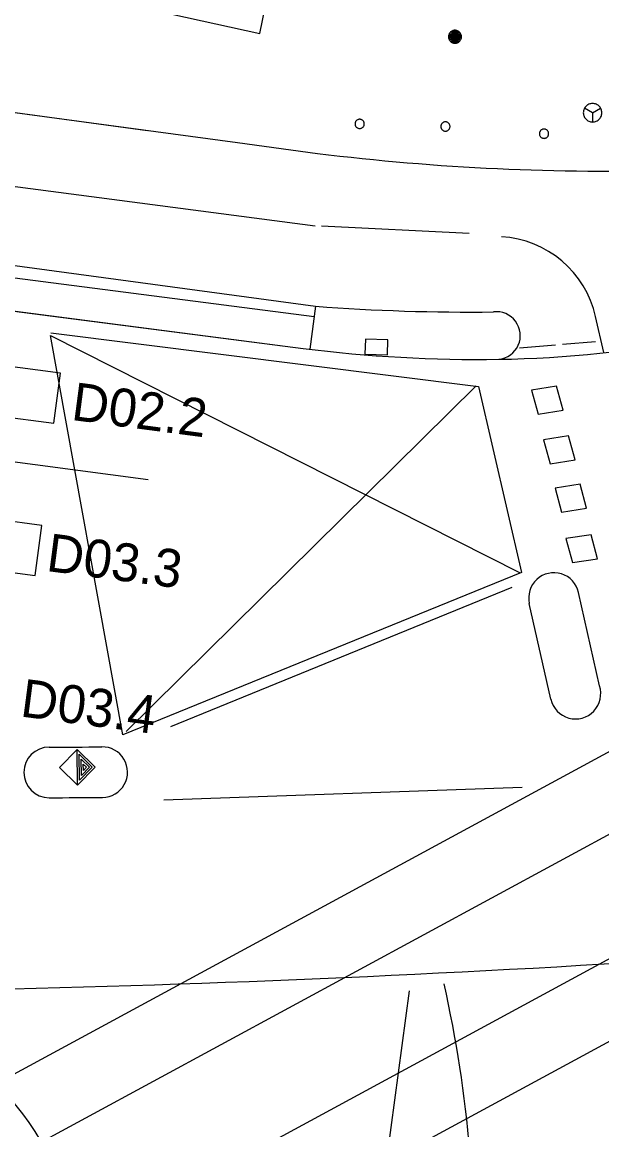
# Model space of a CAD drawing. Extents: x 81065 to 81486, y 452384 to 452681.
# Drawn here: x 81272.43 to 81283.9, y 452511.24 to 452533.14 of the extents above; entities that cross this region are included whole.
import ezdxf

# ---------------------------------------------------------------- set-up
doc = ezdxf.new("R2010")
doc.units = 0
for name, color, linetype in [('B-BH-GR-BOOM-S', 7, 'Continuous'), ('B-BH-IE-MEUBILAIR-WEGMEUBILAIR-VERKEERSBORD-S', 7, 'Continuous'), ('B-BH-IE-MEUBILAIR_WEGMEUBILAIR_BEWEGWIJZERING-S', 7, 'Continuous'), ('B-BH-IE-MEUBILAIR_WEGMEUBILAIR_PAAL-S', 7, 'Continuous'), ('B-BH-VH-KANTOPSLUITING-GV', 7, 'Continuous'), ('B-SB-OG-WEG_SPOOR_TRAM-G', 7, 'Continuous'), ('B-SRI-KOLK_COMBINATIE-S', 7, 'Continuous'), ('B-WE-VW-MARKERING_DWARS_DRIEHOEK_5050-G', 7, 'Continuous'), ('B-WE-VW-MARKERING_DWARS_OVERSTEEK_BLOKSTREEP50-G', 7, 'Continuous'), ('B-WE-VW-MARKERING_LANGS_STREEP_11_010-G', 7, 'Continuous'), ('B-WE-VW-MARKERING_LANGS_STREEP_13_030-G', 7, 'Continuous'), ('B-WE-VW-MARKERING_LANGS_STREEP_30270_010-G', 7, 'Continuous'), ('B-WE-VW-MARKERING_LANGS_STREEP_DOORGETROKKEN_010-G', 7, 'Continuous'), ('N-OI-KL-VRI_LUS_DETECTIE-G', 7, 'Continuous'), ('N-OI-KL-VRI_LUS_DETECTIE-T18', 7, 'Continuous')]:
    doc.layers.add(name, color=color, linetype=linetype)

msp = doc.modelspace()

# ---------------------------------------------------------------- linework, layer by layer
at = {"layer": 'B-BH-GR-BOOM-S'}
for points in [[(81280.864, 452532.856), (81280.865, 452532.842), (81280.867, 452532.829), (81280.87, 452532.816), (81280.875, 452532.804), (81280.881, 452532.792), (81280.889, 452532.78), (81280.897, 452532.77), (81280.907, 452532.76), (81280.917, 452532.752), (81280.929, 452532.744), (81280.941, 452532.738), (81280.953, 452532.733), (81280.966, 452532.73), (81280.979, 452532.728), (81280.993, 452532.727), (81281.006, 452532.728), (81281.02, 452532.73), (81281.033, 452532.733), (81281.045, 452532.738), (81281.057, 452532.744), (81281.069, 452532.752), (81281.079, 452532.76), (81281.089, 452532.77), (81281.097, 452532.78), (81281.105, 452532.792), (81281.111, 452532.804), (81281.115, 452532.816), (81281.119, 452532.829), (81281.121, 452532.842), (81281.122, 452532.856), (81281.121, 452532.869), (81281.119, 452532.883), (81281.115, 452532.896), (81281.111, 452532.908), (81281.105, 452532.92), (81281.097, 452532.932), (81281.089, 452532.942), (81281.079, 452532.952), (81281.069, 452532.96), (81281.057, 452532.968), (81281.045, 452532.974), (81281.033, 452532.978), (81281.02, 452532.982), (81281.006, 452532.984), (81280.993, 452532.985), (81280.979, 452532.984), (81280.966, 452532.982), (81280.953, 452532.978), (81280.941, 452532.974), (81280.929, 452532.968), (81280.917, 452532.96), (81280.907, 452532.952), (81280.897, 452532.942), (81280.889, 452532.932), (81280.881, 452532.92), (81280.875, 452532.908), (81280.87, 452532.896), (81280.867, 452532.883), (81280.865, 452532.869), (81280.864, 452532.856)], [(81280.889, 452532.856), (81280.889, 452532.845), (81280.891, 452532.834), (81280.894, 452532.824), (81280.898, 452532.813), (81280.902, 452532.804), (81280.908, 452532.795), (81280.915, 452532.786), (81280.923, 452532.778), (81280.932, 452532.771), (81280.941, 452532.765), (81280.95, 452532.761), (81280.961, 452532.757), (81280.971, 452532.754), (81280.982, 452532.752), (81280.993, 452532.752), (81281.004, 452532.752), (81281.015, 452532.754), (81281.025, 452532.757), (81281.035, 452532.761), (81281.045, 452532.765), (81281.054, 452532.771), (81281.063, 452532.778), (81281.071, 452532.786), (81281.077, 452532.795), (81281.083, 452532.804), (81281.088, 452532.813), (81281.092, 452532.824), (81281.095, 452532.834), (81281.097, 452532.845), (81281.097, 452532.856), (81281.097, 452532.867), (81281.095, 452532.878), (81281.092, 452532.888), (81281.088, 452532.898), (81281.083, 452532.908), (81281.077, 452532.917), (81281.071, 452532.926), (81281.063, 452532.934), (81281.054, 452532.94), (81281.045, 452532.946), (81281.035, 452532.951), (81281.025, 452532.955), (81281.015, 452532.958), (81281.004, 452532.96), (81280.993, 452532.96), (81280.982, 452532.96), (81280.971, 452532.958), (81280.961, 452532.955), (81280.95, 452532.951), (81280.941, 452532.946), (81280.932, 452532.94), (81280.923, 452532.934), (81280.915, 452532.926), (81280.908, 452532.917), (81280.902, 452532.908), (81280.898, 452532.898), (81280.894, 452532.888), (81280.891, 452532.878), (81280.889, 452532.867), (81280.889, 452532.856)], [(81280.911, 452532.856), (81280.912, 452532.847), (81280.913, 452532.839), (81280.915, 452532.831), (81280.918, 452532.823), (81280.922, 452532.815), (81280.927, 452532.808), (81280.932, 452532.801), (81280.938, 452532.795), (81280.945, 452532.79), (81280.952, 452532.785), (81280.96, 452532.781), (81280.968, 452532.778), (81280.976, 452532.776), (81280.984, 452532.775), (81280.993, 452532.774), (81281.001, 452532.775), (81281.01, 452532.776), (81281.018, 452532.778), (81281.026, 452532.781), (81281.034, 452532.785), (81281.041, 452532.79), (81281.048, 452532.795), (81281.054, 452532.801), (81281.059, 452532.808), (81281.064, 452532.815), (81281.067, 452532.823), (81281.071, 452532.831), (81281.073, 452532.839), (81281.074, 452532.847), (81281.075, 452532.856), (81281.074, 452532.864), (81281.073, 452532.873), (81281.071, 452532.881), (81281.067, 452532.889), (81281.064, 452532.897), (81281.059, 452532.904), (81281.054, 452532.911), (81281.048, 452532.917), (81281.041, 452532.922), (81281.034, 452532.927), (81281.026, 452532.93), (81281.018, 452532.934), (81281.01, 452532.936), (81281.001, 452532.937), (81280.993, 452532.938), (81280.984, 452532.937), (81280.976, 452532.936), (81280.968, 452532.934), (81280.96, 452532.93), (81280.952, 452532.927), (81280.945, 452532.922), (81280.938, 452532.917), (81280.932, 452532.911), (81280.927, 452532.904), (81280.922, 452532.897), (81280.918, 452532.889), (81280.915, 452532.881), (81280.913, 452532.873), (81280.912, 452532.864), (81280.911, 452532.856)], [(81280.934, 452532.856), (81280.935, 452532.85), (81280.936, 452532.844), (81280.937, 452532.838), (81280.939, 452532.832), (81280.942, 452532.827), (81280.946, 452532.821), (81280.949, 452532.817), (81280.954, 452532.812), (81280.958, 452532.809), (81280.964, 452532.805), (81280.969, 452532.802), (81280.975, 452532.8), (81280.981, 452532.799), (81280.987, 452532.798), (81280.993, 452532.797), (81280.999, 452532.798), (81281.005, 452532.799), (81281.011, 452532.8), (81281.017, 452532.802), (81281.022, 452532.805), (81281.027, 452532.809), (81281.032, 452532.812), (81281.037, 452532.817), (81281.04, 452532.821), (81281.044, 452532.827), (81281.047, 452532.832), (81281.049, 452532.838), (81281.05, 452532.844), (81281.051, 452532.85), (81281.052, 452532.856), (81281.051, 452532.862), (81281.05, 452532.868), (81281.049, 452532.874), (81281.047, 452532.88), (81281.044, 452532.885), (81281.04, 452532.89), (81281.037, 452532.895), (81281.032, 452532.9), (81281.027, 452532.903), (81281.022, 452532.907), (81281.017, 452532.91), (81281.011, 452532.912), (81281.005, 452532.913), (81280.999, 452532.914), (81280.993, 452532.915), (81280.987, 452532.914), (81280.981, 452532.913), (81280.975, 452532.912), (81280.969, 452532.91), (81280.964, 452532.907), (81280.958, 452532.903), (81280.954, 452532.9), (81280.949, 452532.895), (81280.946, 452532.89), (81280.942, 452532.885), (81280.939, 452532.88), (81280.937, 452532.874), (81280.936, 452532.868), (81280.935, 452532.862), (81280.934, 452532.856)], [(81280.957, 452532.856), (81280.957, 452532.852), (81280.958, 452532.849), (81280.959, 452532.845), (81280.96, 452532.841), (81280.962, 452532.838), (81280.964, 452532.835), (81280.966, 452532.832), (81280.969, 452532.829), (81280.972, 452532.827), (81280.975, 452532.825), (81280.978, 452532.823), (81280.982, 452532.822), (81280.986, 452532.821), (81280.989, 452532.82), (81280.993, 452532.82), (81280.997, 452532.82), (81281, 452532.821), (81281.004, 452532.822), (81281.008, 452532.823), (81281.011, 452532.825), (81281.014, 452532.827), (81281.017, 452532.829), (81281.019, 452532.832), (81281.022, 452532.835), (81281.024, 452532.838), (81281.026, 452532.841), (81281.027, 452532.845), (81281.028, 452532.849), (81281.029, 452532.852), (81281.029, 452532.856), (81281.029, 452532.86), (81281.028, 452532.863), (81281.027, 452532.867), (81281.026, 452532.871), (81281.024, 452532.874), (81281.022, 452532.877), (81281.019, 452532.88), (81281.017, 452532.882), (81281.014, 452532.885), (81281.011, 452532.887), (81281.008, 452532.889), (81281.004, 452532.89), (81281, 452532.891), (81280.997, 452532.892), (81280.993, 452532.892), (81280.989, 452532.892), (81280.986, 452532.891), (81280.982, 452532.89), (81280.978, 452532.889), (81280.975, 452532.887), (81280.972, 452532.885), (81280.969, 452532.882), (81280.966, 452532.88), (81280.964, 452532.877), (81280.962, 452532.874), (81280.96, 452532.871), (81280.959, 452532.867), (81280.958, 452532.863), (81280.957, 452532.86), (81280.957, 452532.856)], [(81280.98, 452532.856), (81280.98, 452532.855), (81280.98, 452532.853), (81280.981, 452532.852), (81280.981, 452532.851), (81280.982, 452532.85), (81280.983, 452532.848), (81280.983, 452532.847), (81280.984, 452532.846), (81280.985, 452532.846), (81280.987, 452532.845), (81280.988, 452532.844), (81280.989, 452532.844), (81280.99, 452532.843), (81280.992, 452532.843), (81280.993, 452532.843), (81280.994, 452532.843), (81280.996, 452532.843), (81280.997, 452532.844), (81280.998, 452532.844), (81280.999, 452532.845), (81281.001, 452532.846), (81281.002, 452532.846), (81281.003, 452532.847), (81281.003, 452532.848), (81281.004, 452532.85), (81281.005, 452532.851), (81281.005, 452532.852), (81281.006, 452532.853), (81281.006, 452532.855), (81281.006, 452532.856), (81281.006, 452532.857), (81281.006, 452532.859), (81281.005, 452532.86), (81281.005, 452532.861), (81281.004, 452532.862), (81281.003, 452532.864), (81281.003, 452532.865), (81281.002, 452532.866), (81281.001, 452532.866), (81280.999, 452532.867), (81280.998, 452532.868), (81280.997, 452532.868), (81280.996, 452532.869), (81280.994, 452532.869), (81280.993, 452532.869), (81280.992, 452532.869), (81280.99, 452532.869), (81280.989, 452532.868), (81280.988, 452532.868), (81280.987, 452532.867), (81280.985, 452532.866), (81280.984, 452532.866), (81280.983, 452532.865), (81280.983, 452532.864), (81280.982, 452532.862), (81280.981, 452532.861), (81280.981, 452532.86), (81280.98, 452532.859), (81280.98, 452532.857), (81280.98, 452532.856)]]:
    msp.add_lwpolyline(points, dxfattribs=at)
at = {"layer": 'B-BH-IE-MEUBILAIR-WEGMEUBILAIR-VERKEERSBORD-S'}
msp.add_lwpolyline([(81273.522, 452518.056), (81273.164, 452518.405), (81273.513, 452518.763)], dxfattribs=at)
for points in [[(81273.522, 452518.056), (81273.513, 452518.763), (81273.871, 452518.414)], [(81273.561, 452518.153), (81273.555, 452518.666), (81273.815, 452518.413)], [(81273.6, 452518.25), (81273.595, 452518.571), (81273.758, 452518.412)], [(81273.639, 452518.347), (81273.637, 452518.474), (81273.701, 452518.412)]]:
    msp.add_lwpolyline(points, close=True, dxfattribs=at)
at = {"layer": 'B-BH-IE-MEUBILAIR_WEGMEUBILAIR_BEWEGWIJZERING-S'}
for q in [(81283.557, 452531.444), (81283.875, 452531.444), (81283.716, 452531.17)]:
    msp.add_line((81283.716, 452531.353), q, dxfattribs=at)
msp.add_lwpolyline([(81283.899, 452531.353), (81283.898, 452531.372), (81283.895, 452531.391), (81283.89, 452531.41), (81283.883, 452531.427), (81283.874, 452531.444), (81283.864, 452531.461), (81283.852, 452531.475), (81283.838, 452531.489), (81283.824, 452531.501), (81283.807, 452531.511), (81283.79, 452531.52), (81283.773, 452531.527), (81283.754, 452531.532), (81283.735, 452531.535), (81283.716, 452531.536), (81283.697, 452531.535), (81283.678, 452531.532), (81283.659, 452531.527), (81283.641, 452531.52), (81283.624, 452531.511), (81283.608, 452531.501), (81283.593, 452531.489), (81283.58, 452531.475), (81283.568, 452531.461), (81283.557, 452531.444), (81283.549, 452531.427), (81283.542, 452531.41), (81283.537, 452531.391), (81283.534, 452531.372), (81283.533, 452531.353), (81283.534, 452531.334), (81283.537, 452531.315), (81283.542, 452531.296), (81283.549, 452531.278), (81283.557, 452531.261), (81283.568, 452531.245), (81283.58, 452531.23), (81283.593, 452531.217), (81283.608, 452531.205), (81283.624, 452531.194), (81283.641, 452531.186), (81283.659, 452531.179), (81283.678, 452531.174), (81283.697, 452531.171), (81283.716, 452531.17), (81283.735, 452531.171), (81283.754, 452531.174), (81283.773, 452531.179), (81283.79, 452531.186), (81283.807, 452531.194), (81283.824, 452531.205), (81283.838, 452531.217), (81283.852, 452531.23), (81283.864, 452531.245), (81283.874, 452531.261), (81283.883, 452531.278), (81283.89, 452531.296), (81283.895, 452531.315), (81283.898, 452531.334), (81283.899, 452531.353)], dxfattribs=at)
at = {"layer": 'B-BH-IE-MEUBILAIR_WEGMEUBILAIR_PAAL-S'}
for points in [[(81279.015, 452531.133), (81279.016, 452531.123), (81279.017, 452531.114), (81279.02, 452531.104), (81279.023, 452531.095), (81279.027, 452531.087), (81279.033, 452531.079), (81279.039, 452531.071), (81279.045, 452531.065), (81279.053, 452531.059), (81279.061, 452531.053), (81279.07, 452531.049), (81279.078, 452531.046), (81279.088, 452531.043), (81279.097, 452531.042), (81279.107, 452531.041), (81279.116, 452531.042), (81279.126, 452531.043), (81279.135, 452531.046), (81279.144, 452531.049), (81279.153, 452531.053), (81279.161, 452531.059), (81279.168, 452531.065), (81279.175, 452531.071), (81279.181, 452531.079), (81279.186, 452531.087), (81279.19, 452531.095), (81279.194, 452531.104), (81279.196, 452531.114), (81279.198, 452531.123), (81279.198, 452531.133), (81279.198, 452531.142), (81279.196, 452531.152), (81279.194, 452531.161), (81279.19, 452531.17), (81279.186, 452531.178), (81279.181, 452531.186), (81279.175, 452531.194), (81279.168, 452531.201), (81279.161, 452531.207), (81279.153, 452531.212), (81279.144, 452531.216), (81279.135, 452531.22), (81279.126, 452531.222), (81279.116, 452531.224), (81279.107, 452531.224), (81279.097, 452531.224), (81279.088, 452531.222), (81279.078, 452531.22), (81279.07, 452531.216), (81279.061, 452531.212), (81279.053, 452531.207), (81279.045, 452531.201), (81279.039, 452531.194), (81279.033, 452531.186), (81279.027, 452531.178), (81279.023, 452531.17), (81279.02, 452531.161), (81279.017, 452531.152), (81279.016, 452531.142), (81279.015, 452531.133)], [(81280.712, 452531.082), (81280.713, 452531.072), (81280.714, 452531.063), (81280.717, 452531.053), (81280.72, 452531.044), (81280.724, 452531.036), (81280.73, 452531.028), (81280.736, 452531.02), (81280.742, 452531.014), (81280.75, 452531.008), (81280.758, 452531.002), (81280.767, 452530.998), (81280.775, 452530.995), (81280.785, 452530.992), (81280.794, 452530.991), (81280.804, 452530.99), (81280.813, 452530.991), (81280.823, 452530.992), (81280.832, 452530.995), (81280.841, 452530.998), (81280.85, 452531.002), (81280.858, 452531.008), (81280.865, 452531.014), (81280.872, 452531.02), (81280.878, 452531.028), (81280.883, 452531.036), (81280.887, 452531.044), (81280.891, 452531.053), (81280.893, 452531.063), (81280.895, 452531.072), (81280.895, 452531.082), (81280.895, 452531.091), (81280.893, 452531.101), (81280.891, 452531.11), (81280.887, 452531.119), (81280.883, 452531.127), (81280.878, 452531.135), (81280.872, 452531.143), (81280.865, 452531.15), (81280.858, 452531.156), (81280.85, 452531.161), (81280.841, 452531.165), (81280.832, 452531.169), (81280.823, 452531.171), (81280.813, 452531.173), (81280.804, 452531.173), (81280.794, 452531.173), (81280.785, 452531.171), (81280.775, 452531.169), (81280.767, 452531.165), (81280.758, 452531.161), (81280.75, 452531.156), (81280.742, 452531.15), (81280.736, 452531.143), (81280.73, 452531.135), (81280.724, 452531.127), (81280.72, 452531.119), (81280.717, 452531.11), (81280.714, 452531.101), (81280.713, 452531.091), (81280.712, 452531.082)], [(81282.664, 452530.939), (81282.665, 452530.929), (81282.666, 452530.92), (81282.669, 452530.91), (81282.672, 452530.901), (81282.676, 452530.893), (81282.682, 452530.885), (81282.688, 452530.877), (81282.694, 452530.871), (81282.702, 452530.865), (81282.71, 452530.859), (81282.719, 452530.855), (81282.727, 452530.852), (81282.737, 452530.849), (81282.746, 452530.848), (81282.756, 452530.847), (81282.765, 452530.848), (81282.775, 452530.849), (81282.784, 452530.852), (81282.793, 452530.855), (81282.802, 452530.859), (81282.81, 452530.865), (81282.817, 452530.871), (81282.824, 452530.877), (81282.83, 452530.885), (81282.835, 452530.893), (81282.839, 452530.901), (81282.843, 452530.91), (81282.845, 452530.92), (81282.847, 452530.929), (81282.847, 452530.939), (81282.847, 452530.948), (81282.845, 452530.958), (81282.843, 452530.967), (81282.839, 452530.976), (81282.835, 452530.984), (81282.83, 452530.992), (81282.824, 452531), (81282.817, 452531.007), (81282.81, 452531.013), (81282.802, 452531.018), (81282.793, 452531.022), (81282.784, 452531.026), (81282.775, 452531.028), (81282.765, 452531.03), (81282.756, 452531.03), (81282.746, 452531.03), (81282.737, 452531.028), (81282.727, 452531.026), (81282.719, 452531.022), (81282.71, 452531.018), (81282.702, 452531.013), (81282.694, 452531.007), (81282.688, 452531), (81282.682, 452530.992), (81282.676, 452530.984), (81282.672, 452530.976), (81282.669, 452530.967), (81282.666, 452530.958), (81282.665, 452530.948), (81282.664, 452530.939)]]:
    msp.add_lwpolyline(points, dxfattribs=at)
at = {"layer": 'B-BH-VH-KANTOPSLUITING-GV'}
for p, q in [((81246.656, 452534.817), (81276.688, 452530.764)), ((81245.674, 452531.923), (81278.234, 452527.528)), ((81272, 452531.396), (81274.91, 452531.004)), ((81276.688, 452530.764), (81278.27, 452530.55)), ((81265.878, 452528.256), (81277.986, 452526.694)), ((81278.234, 452527.528), (81278.123, 452526.681)), ((81283.855, 452520.021), (81283.438, 452521.867)), ((81282.89, 452519.755), (81282.463, 452521.647))]:
    msp.add_line(p, q, dxfattribs=at)
for points in [[(81275.387, 452533.305), (81277.129, 452532.918), (81281.869, 452556.046), (81280.167, 452556.385)], [(81243.726, 452531.159), (81265.878, 452528.256), (81277.986, 452526.694)], [(81265.891, 452528.91), (81278.207, 452527.321)]]:
    msp.add_lwpolyline(points, dxfattribs=at)
for centre, radius, start, end in [((81283.999, 452576.959), 46.761, 262.9631, 271.7285), ((81281.272, 452566.92), 39.509, 265.5905, 270.6987), ((81281.815, 452526.947), 0.471, 275.3312, 97.4365), ((81281.445, 452553.872), 27.398, 262.7477, 270.8654), ((81281.54, 452548.965), 22.489, 270.8118, 281.0417), ((81282.951, 452521.757), 0.5, 12.7307, 192.7307), ((81283.378, 452519.865), 0.5, 192.7307, 18.1304), ((81272.962, 452518.308), 0.5, 89.9379, 269.9379), ((81272.985, 452613.808), 95, 269.98634, 270.61491), ((81274.013, 452518.313), 0.5, 270.2593, 90.9705), ((81272.985, 452613.808), 96, 269.98584, 270.61491), ((81267.651, 452507.942), 6, 346.0023, 51.5109)]:
    msp.add_arc(centre, radius, start, end, dxfattribs=at)
at = {"layer": 'B-SB-OG-WEG_SPOOR_TRAM-G'}
for p, q in [((81288.285, 452521.011), (81250, 452500.286)), ((81288.969, 452519.749), (81250, 452498.654)), ((81250, 452496.192), (81288.558, 452517.065)), ((81250, 452494.56), (81289.242, 452515.803))]:
    msp.add_line(p, q, dxfattribs=at)
at = {"layer": 'B-SRI-KOLK_COMBINATIE-S'}
for p, q in [((81279.219, 452526.877), (81279.209, 452526.582)), ((81279.667, 452526.861), (81279.219, 452526.877)), ((81279.656, 452526.566), (81279.667, 452526.861)), ((81279.209, 452526.582), (81279.656, 452526.566))]:
    msp.add_line(p, q, dxfattribs=at)
at = {"layer": 'B-WE-VW-MARKERING_DWARS_DRIEHOEK_5050-G'}
for points in [[(81282.981, 452526.758), (81282.267, 452526.698)], [(81283.772, 452526.824), (81283.118, 452526.769)]]:
    msp.add_lwpolyline(points, dxfattribs=at)
at = {"layer": 'B-WE-VW-MARKERING_DWARS_OVERSTEEK_BLOKSTREEP50-G'}
for points in [[(81283.004, 452525.945), (81282.508, 452525.869), (81282.637, 452525.395), (81283.133, 452525.471)], [(81283.241, 452524.963), (81282.746, 452524.888), (81282.875, 452524.413), (81283.37, 452524.489)], [(81283.468, 452524.006), (81282.973, 452523.93), (81283.102, 452523.456), (81283.597, 452523.532)], [(81283.685, 452523.007), (81283.189, 452522.931), (81283.318, 452522.457), (81283.814, 452522.533)]]:
    msp.add_lwpolyline(points, close=True, dxfattribs=at)
at = {"layer": 'B-WE-VW-MARKERING_LANGS_STREEP_11_010-G'}
for p, q in [((81275.368, 452519.216), (81282.127, 452521.968)), ((81275.228, 452517.763), (81282.323, 452518.014))]:
    msp.add_line(p, q, dxfattribs=at)
msp.add_arc((81263.823, 452852.559), 338.637, 271.02728, 273.56485, dxfattribs=at)
at = {"layer": 'B-WE-VW-MARKERING_LANGS_STREEP_13_030-G'}
msp.add_line((81255.474, 452526.651), (81274.923, 452524.102), dxfattribs=at)
at = {"layer": 'B-WE-VW-MARKERING_LANGS_STREEP_30270_010-G'}
for p, q in [((81249.168, 452532.914), (81278.225, 452529.119)), ((81278.352, 452529.119), (81281.274, 452528.971))]:
    msp.add_line(p, q, dxfattribs=at)
at = {"layer": 'B-WE-VW-MARKERING_LANGS_STREEP_DOORGETROKKEN_010-G'}
for p, q in [((81283.942, 452526.613), (81283.775, 452527.321)), ((81281.415, 452525.95), (81274.488, 452519.118)), ((81280.086, 452513.991), (81279.507, 452509.697))]:
    msp.add_line(p, q, dxfattribs=at)
msp.add_lwpolyline([(81272.994, 452526.998), (81281.457, 452525.937), (81282.309, 452522.262), (81274.419, 452519.048), (81272.988, 452526.949), (81272.988, 452526.949), (81282.267, 452522.262)], dxfattribs=at)
for centre, radius, start, end in [((81281.792, 452526.873), 2.033, 12.7202, 86.5681), ((81257.338, 452508.824), 24.031, 4.7533, 12.7482)]:
    msp.add_arc(centre, radius, start, end, dxfattribs=at)
at = {"layer": 'N-OI-KL-VRI_LUS_DETECTIE-G'}
for p, q in [((81273.184, 452526.205), (81253.354, 452528.804)), ((81253.224, 452527.813), (81273.054, 452525.214)), ((81273.054, 452525.214), (81273.184, 452526.205)), ((81272.816, 452523.192), (81252.986, 452525.791)), ((81252.856, 452524.799), (81272.686, 452522.2)), ((81272.686, 452522.2), (81272.816, 452523.192))]:
    msp.add_line(p, q, dxfattribs=at)

# ---------------------------------------------------------------- texts
at = {"layer": 'N-OI-KL-VRI_LUS_DETECTIE-T18'}
for s, p in [('D02.2', (81273.381, 452525.281)), ('D03.3', (81272.886, 452522.294)), ('D03.4', (81272.372, 452519.417))]:
    msp.add_text(s, height=0.75, rotation=352.5333, dxfattribs=at).set_placement(p)

doc.saveas('drawing.dxf')
